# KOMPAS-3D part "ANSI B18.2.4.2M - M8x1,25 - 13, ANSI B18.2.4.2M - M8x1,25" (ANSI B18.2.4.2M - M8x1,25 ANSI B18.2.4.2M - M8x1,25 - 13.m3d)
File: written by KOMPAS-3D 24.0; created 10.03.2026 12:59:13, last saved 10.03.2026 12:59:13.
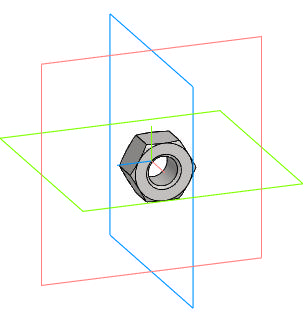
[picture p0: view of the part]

Document properties: Автор: R2D2; Полное имя файла: E:\Работа\Зайцев\BV3232P(4pc)-FP-3WL-F-ISO-H Кран шаровой DN.ru Ду15-100 Ру16\DN65\исходные материалы\ANSI B18.2.4.2M - M8x1,25 ANSI B18.2.4.2M - M8x1,25 - 13.m3d

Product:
- Body: Solid1  | qty 1
- Part/product: ANSI B18.2.4.2M - M8x1,25 - 13  | designation ANSI B18.2.4.2M - M8x1,25
    Комментарий: Типы метрических   шестигранных гаек   2
    additional columns: Сталь, мягкая

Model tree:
1. Solid1  (labels: Solid1)

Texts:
  ANSI B18.2.4.2M - M8x1,25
